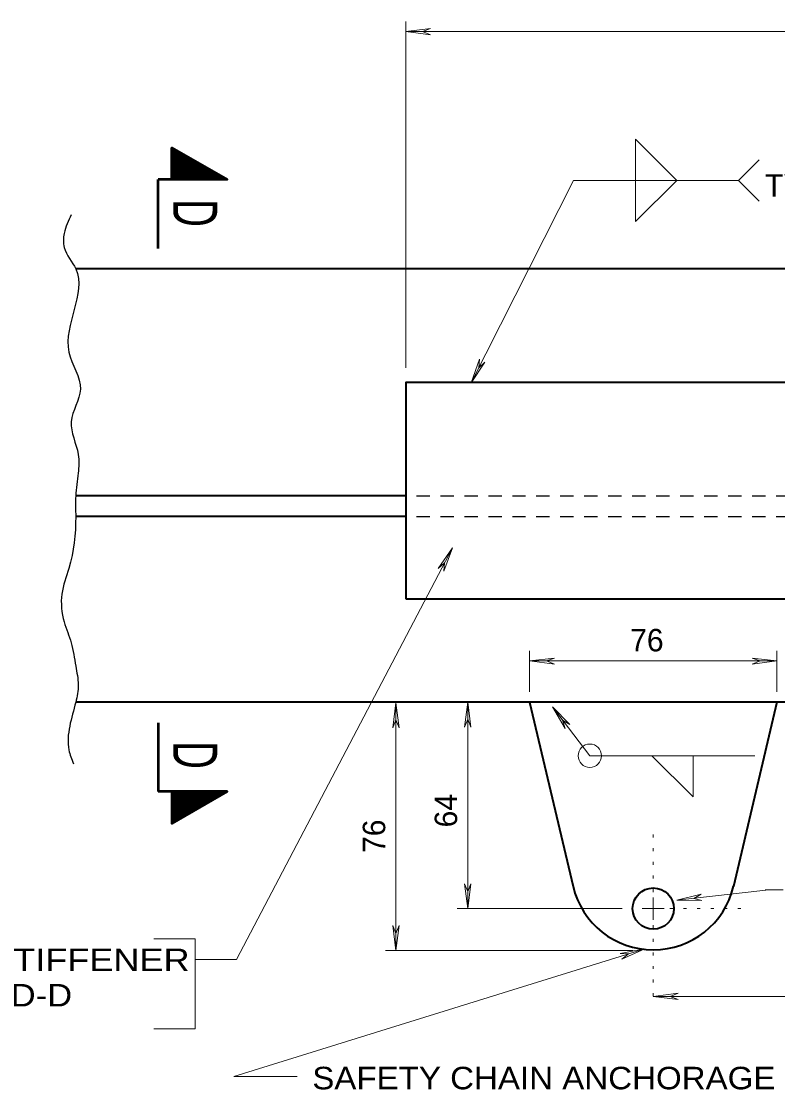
# Model space of a CAD drawing. Extents: x 312583 to 312854, y 144419 to 144597.
# Drawn here: x 312767.21 to 312792.77, y 144484.6 to 144520.68 of the extents above; entities that cross this region are included whole.
import ezdxf
from ezdxf.enums import TextEntityAlignment as Align

# ---------------------------------------------------------------- set-up
doc = ezdxf.new("R2010")
doc.units = 0
doc.header["$LTSCALE"] = 0.3
doc.linetypes.add('DOTTED', pattern=[1.5, 0.3, -1.2])
doc.linetypes.add('SHORT_DASHED', pattern=[2.7, 1.5, -1.2])
doc.layers.add('1', color=7, linetype='Continuous', lineweight=13)

msp = doc.modelspace()

# ---------------------------------------------------------------- linework, layer by layer
at = {"layer": '1'}
for p, q in [((312780.2009, 144508.9729), (312780.2009, 144520.6799)), ((312780.2009, 144520.3349), (312781.0366, 144520.4346)), ((312780.2009, 144520.3349), (312781.0366, 144520.2276)), ((312781.0366, 144520.4346), (312780.7683, 144520.3349)), ((312781.0366, 144520.2276), (312780.7683, 144520.3349)), ((312782.4089, 144508.4746), (312785.8666, 144515.3056)), ((312791.4403, 144515.3056), (312792.1379, 144514.6079)), ((312782.4089, 144508.4746), (312782.6926, 144509.2719)), ((312782.4089, 144508.4746), (312782.8766, 144509.1722)), ((312782.6926, 144509.2719), (312782.6696, 144508.9806)), ((312782.8766, 144509.1722), (312782.6696, 144508.9806)), ((312781.7803, 144502.9009), (312774.4739, 144488.9936)), ((312781.7803, 144502.9009), (312781.2973, 144502.2032)), ((312781.7803, 144502.9009), (312781.4813, 144502.1112)), ((312781.2973, 144502.2032), (312781.5119, 144502.3949)), ((312781.4813, 144502.1112), (312781.5119, 144502.3949)), ((312784.3793, 144499.4202), (312784.3793, 144498.0326)), ((312792.7436, 144499.4202), (312792.7436, 144498.0326)), ((312784.3793, 144499.0752), (312785.2226, 144499.1749)), ((312784.3793, 144499.0752), (312792.7436, 144499.0752)), ((312784.3793, 144499.0752), (312785.2226, 144498.9679)), ((312785.2226, 144499.1749), (312784.9543, 144499.0752)), ((312785.2226, 144498.9679), (312784.9543, 144499.0752)), ((312791.9079, 144499.1749), (312792.1763, 144499.0752)), ((312792.7436, 144499.0752), (312791.9079, 144499.1749)), ((312791.9079, 144498.9679), (312792.1763, 144499.0752)), ((312792.7436, 144499.0752), (312791.9079, 144498.9679)), ((312779.8636, 144497.6569), (312779.7639, 144496.8212)), ((312779.8636, 144489.2926), (312779.8636, 144497.6569)), ((312779.8636, 144497.6569), (312779.9709, 144496.8212)), ((312782.2939, 144497.6799), (312782.1866, 144496.8442)), ((312782.2939, 144490.7109), (312782.2939, 144497.6799)), ((312782.2939, 144497.6799), (312782.3936, 144496.8442)), ((312786.4186, 144495.8706), (312785.1536, 144497.5266)), ((312785.1536, 144497.5266), (312785.7439, 144496.9286)), ((312785.1536, 144497.5266), (312785.5829, 144496.7982)), ((312779.7639, 144496.8212), (312779.8636, 144497.0896)), ((312779.9709, 144496.8212), (312779.8636, 144497.0896)), ((312782.1866, 144496.8442), (312782.2939, 144497.1126)), ((312782.3936, 144496.8442), (312782.2939, 144497.1126)), ((312785.7439, 144496.9286), (312785.4986, 144497.0742)), ((312785.5829, 144496.7982), (312785.4986, 144497.0742)), ((312791.9923, 144495.8706), (312786.4186, 144495.8706)), ((312782.1866, 144491.5466), (312782.2939, 144491.2859)), ((312782.2939, 144490.7109), (312782.1866, 144491.5466)), ((312782.3936, 144491.5466), (312782.2939, 144491.2859)), ((312782.2939, 144490.7109), (312782.3936, 144491.5466)), ((312788.5653, 144490.7109), (312788.5653, 144491.0866)), ((312792.4676, 144491.3472), (312789.3549, 144490.9946)), ((312789.3549, 144490.9946), (312790.1829, 144491.1939)), ((312790.1829, 144491.1939), (312789.9299, 144491.0559)), ((312792.3449, 144491.3472), (312792.9506, 144491.3472)), ((312787.5149, 144490.7109), (312781.9413, 144490.7109)), ((312788.5653, 144490.7109), (312788.1896, 144490.7109)), ((312788.5653, 144490.7109), (312788.9333, 144490.7109)), ((312788.5653, 144490.7109), (312788.5653, 144490.3352)), ((312789.3549, 144490.9946), (312790.2059, 144490.9869)), ((312790.2059, 144490.9869), (312789.9299, 144491.0559)), ((312779.7639, 144490.1359), (312779.8636, 144489.8676)), ((312779.8636, 144489.2926), (312779.7639, 144490.1359)), ((312779.9709, 144490.1359), (312779.8636, 144489.8676)), ((312779.8636, 144489.2926), (312779.9709, 144490.1359)), ((312771.6833, 144489.6912), (312773.0786, 144489.6912)), ((312773.0786, 144486.6476), (312773.0786, 144489.6912)), ((312774.3896, 144485.0343), (312788.2739, 144489.3462)), ((312787.8829, 144489.2926), (312779.5186, 144489.2926)), ((312788.2739, 144489.3462), (312787.4392, 144489.1934)), ((312788.2739, 144489.3462), (312787.5017, 144489.0004)), ((312773.0786, 144488.9936), (312774.4739, 144488.9936)), ((312787.4392, 144489.1934), (312787.7281, 144489.1774)), ((312787.5017, 144489.0004), (312787.7281, 144489.1774)), ((312788.5653, 144487.7439), (312789.4009, 144487.8512)), ((312789.4009, 144487.8512), (312789.1326, 144487.7439)), ((312810.8676, 144487.7439), (312788.5653, 144487.7439)), ((312788.5653, 144487.7439), (312789.4009, 144487.6442)), ((312789.4009, 144487.6442), (312789.1326, 144487.7439)), ((312771.6833, 144486.6476), (312773.0786, 144486.6476)), ((312774.3896, 144485.0343), (312776.5297, 144485.0343))]:
    msp.add_line(p, q, dxfattribs=at)
at = {"layer": '1', "lineweight": 35}
for p, q in [((312772.2966, 144516.3789), (312772.3119, 144516.3942)), ((312772.2966, 144516.3406), (312772.3349, 144516.3866)), ((312772.2966, 144516.2869), (312772.3503, 144516.3712)), ((312772.2966, 144516.2409), (312772.3733, 144516.3559)), ((312772.2966, 144516.1872), (312772.3963, 144516.3482)), ((312772.2966, 144516.1489), (312772.4116, 144516.3406)), ((312772.2966, 144516.1029), (312772.4269, 144516.3252)), ((312772.2966, 144516.0569), (312772.4499, 144516.3176)), ((312772.2966, 144516.0109), (312772.4729, 144516.3099)), ((312772.2966, 144515.9649), (312772.4959, 144516.2946)), ((312772.2966, 144515.9112), (312772.5113, 144516.2869)), ((312772.2966, 144515.8652), (312772.5343, 144516.2716)), ((312772.2966, 144515.8269), (312772.5573, 144516.2639)), ((312772.2966, 144515.7732), (312772.5726, 144516.2486)), ((312772.2966, 144515.7272), (312772.5956, 144516.2409)), ((312772.2966, 144515.6812), (312772.6109, 144516.2256)), ((312772.2966, 144515.6352), (312772.6339, 144516.2102)), ((312772.2966, 144515.5892), (312772.6569, 144516.2026)), ((312772.2966, 144515.5432), (312772.6723, 144516.1872)), ((312772.2966, 144515.4972), (312772.6953, 144516.1719)), ((312772.2966, 144515.4436), (312772.7183, 144516.1642)), ((312772.2966, 144515.4052), (312772.7259, 144516.1489)), ((312772.2966, 144515.3592), (312772.7566, 144516.1412)), ((312772.3119, 144515.3362), (312772.7719, 144516.1259)), ((312772.3426, 144515.3362), (312772.7949, 144516.1259)), ((312772.3733, 144515.3362), (312772.8179, 144516.1029)), ((312772.3963, 144515.3362), (312772.8333, 144516.1029)), ((312772.4269, 144515.3362), (312772.8563, 144516.0799)), ((312772.4499, 144515.3439), (312772.8793, 144516.0799)), ((312772.4729, 144515.3439), (312772.8946, 144516.0646)), ((312772.4959, 144515.3362), (312772.9176, 144516.0569)), ((312772.5266, 144515.3362), (312772.9406, 144516.0416)), ((312772.5573, 144515.3362), (312772.9483, 144516.0262)), ((312772.5803, 144515.3362), (312772.9713, 144516.0186)), ((312772.6109, 144515.3362), (312772.9943, 144516.0032)), ((312772.6416, 144515.3362), (312773.0173, 144515.9879)), ((312772.6646, 144515.3362), (312773.0326, 144515.9802)), ((312772.6953, 144515.3439), (312773.0556, 144515.9649)), ((312772.7183, 144515.3362), (312773.0786, 144515.9572)), ((312772.7413, 144515.3362), (312773.0939, 144515.9419)), ((312772.7643, 144515.3362), (312773.1169, 144515.9342)), ((312772.7949, 144515.3362), (312773.1399, 144515.9189)), ((312772.8256, 144515.3362), (312773.1553, 144515.9112)), ((312772.8563, 144515.3362), (312773.1783, 144515.8959)), ((312772.8793, 144515.3362), (312773.1936, 144515.8882)), ((312772.9099, 144515.3362), (312773.2089, 144515.8806)), ((312772.9329, 144515.3439), (312773.2396, 144515.8652)), ((312772.9636, 144515.3362), (312773.2549, 144515.8576)), ((312772.9789, 144515.3362), (312773.2779, 144515.8346)), ((312773.0096, 144515.3362), (312773.3009, 144515.8346)), ((312773.0403, 144515.3362), (312773.3163, 144515.8192)), ((312773.0633, 144515.3362), (312773.3393, 144515.8116)), ((312773.0939, 144515.3362), (312773.3623, 144515.7962)), ((312773.1246, 144515.3362), (312773.3776, 144515.7886)), ((312773.1476, 144515.3362), (312773.4006, 144515.7732)), ((312773.1783, 144515.3362), (312773.4236, 144515.7656)), ((312773.2089, 144515.3362), (312773.4313, 144515.7502)), ((312773.2243, 144515.3362), (312773.4543, 144515.7426)), ((312773.2473, 144515.3362), (312773.4773, 144515.7272)), ((312773.2779, 144515.3362), (312773.5003, 144515.7196)), ((312773.3086, 144515.3362), (312773.5156, 144515.7042)), ((312773.3393, 144515.3362), (312773.5386, 144515.6889)), ((312773.3623, 144515.3362), (312773.5616, 144515.6812)), ((312773.3929, 144515.3362), (312773.5769, 144515.6659)), ((312773.4083, 144515.3362), (312773.5999, 144515.6506)), ((312773.4389, 144515.3362), (312773.6229, 144515.6429)), ((312773.4619, 144515.3362), (312773.6383, 144515.6352)), ((312773.4926, 144515.3362), (312773.6536, 144515.6199)), ((312773.5233, 144515.3362), (312773.6766, 144515.6122)), ((312773.5463, 144515.3362), (312773.6996, 144515.6046)), ((312773.5769, 144515.3362), (312773.7226, 144515.5892)), ((312773.5999, 144515.3362), (312773.7379, 144515.5816)), ((312773.6306, 144515.3362), (312773.7609, 144515.5662)), ((312773.6536, 144515.3362), (312773.7839, 144515.5586)), ((312773.6766, 144515.3362), (312773.7993, 144515.5432)), ((312773.7073, 144515.3362), (312773.8223, 144515.5356)), ((312773.7303, 144515.3362), (312773.8453, 144515.5202)), ((312773.7609, 144515.3362), (312773.8606, 144515.5049)), ((312773.7916, 144515.3362), (312773.8836, 144515.4972)), ((312773.8223, 144515.3362), (312773.8989, 144515.4819)), ((312773.8453, 144515.3362), (312773.9219, 144515.4666)), ((312773.8759, 144515.3362), (312773.9449, 144515.4589)), ((312773.8989, 144515.3362), (312773.9603, 144515.4436)), ((312773.9219, 144515.3362), (312773.9833, 144515.4359)), ((312773.9449, 144515.3362), (312773.9986, 144515.4206)), ((312773.9756, 144515.3362), (312774.0216, 144515.4129)), ((312774.0063, 144515.3362), (312774.0446, 144515.3976)), ((312774.0293, 144515.3362), (312774.0599, 144515.3899)), ((312774.0599, 144515.3362), (312774.0829, 144515.3746)), ((312774.0829, 144515.3362), (312774.1059, 144515.3669)), ((312774.1136, 144515.3362), (312774.1213, 144515.3592)), ((312774.1443, 144515.3362), (312774.1443, 144515.3439)), ((312772.2966, 144494.6439), (312772.7566, 144493.8542)), ((312772.2966, 144494.5902), (312772.7259, 144493.8466)), ((312772.2966, 144494.5519), (312772.7183, 144493.8312)), ((312772.2966, 144494.4982), (312772.6953, 144493.8236)), ((312772.2966, 144494.4522), (312772.6723, 144493.8082)), ((312772.2966, 144494.4139), (312772.6569, 144493.7929)), ((312772.2966, 144494.3679), (312772.6339, 144493.7852)), ((312772.3119, 144494.6669), (312772.7719, 144493.8696)), ((312772.3426, 144494.6669), (312772.7949, 144493.8772)), ((312772.3733, 144494.6669), (312772.8179, 144493.8926)), ((312772.3963, 144494.6669), (312772.8333, 144493.9002)), ((312772.4269, 144494.6669), (312772.8563, 144493.9156)), ((312772.4499, 144494.6592), (312772.8793, 144493.9232)), ((312772.4729, 144494.6592), (312772.8946, 144493.9386)), ((312772.4959, 144494.6669), (312772.9176, 144493.9386)), ((312772.5266, 144494.6669), (312772.9406, 144493.9616)), ((312772.5573, 144494.6669), (312772.9483, 144493.9692)), ((312772.5803, 144494.6669), (312772.9713, 144493.9846)), ((312772.6109, 144494.6669), (312772.9943, 144493.9922)), ((312772.6416, 144494.6669), (312773.0173, 144494.0076)), ((312772.6646, 144494.6669), (312773.0326, 144494.0152)), ((312772.6953, 144494.6592), (312773.0556, 144494.0306)), ((312772.7183, 144494.6669), (312773.0786, 144494.0382)), ((312772.7413, 144494.6669), (312773.0939, 144494.0536)), ((312772.7643, 144494.6669), (312773.1169, 144494.0612)), ((312772.7949, 144494.6669), (312773.1399, 144494.0766)), ((312772.8256, 144494.6669), (312773.1553, 144494.0842)), ((312772.8563, 144494.6669), (312773.1783, 144494.0996)), ((312772.8793, 144494.6669), (312773.1936, 144494.1072)), ((312772.9099, 144494.6669), (312773.2089, 144494.1226)), ((312772.9329, 144494.6592), (312773.2396, 144494.1302)), ((312772.9636, 144494.6669), (312773.2549, 144494.1456)), ((312772.9789, 144494.6669), (312773.2779, 144494.1609)), ((312773.0096, 144494.6669), (312773.3009, 144494.1686)), ((312773.0403, 144494.6669), (312773.3163, 144494.1839)), ((312773.0633, 144494.6669), (312773.3393, 144494.1839)), ((312773.0939, 144494.6669), (312773.3623, 144494.2069)), ((312773.1246, 144494.6669), (312773.3776, 144494.2069)), ((312773.1476, 144494.6669), (312773.4006, 144494.2299)), ((312773.1783, 144494.6669), (312773.4236, 144494.2299)), ((312773.2089, 144494.6669), (312773.4313, 144494.2452)), ((312773.2243, 144494.6669), (312773.4543, 144494.2529)), ((312773.2473, 144494.6669), (312773.4773, 144494.2682)), ((312773.2779, 144494.6669), (312773.5003, 144494.2759)), ((312773.3086, 144494.6669), (312773.5156, 144494.2912)), ((312773.3393, 144494.6669), (312773.5386, 144494.3066)), ((312773.3623, 144494.6669), (312773.5616, 144494.3142)), ((312773.3929, 144494.6669), (312773.5769, 144494.3296)), ((312773.4083, 144494.6669), (312773.5999, 144494.3449)), ((312773.4389, 144494.6669), (312773.6229, 144494.3526)), ((312773.4619, 144494.6669), (312773.6383, 144494.3679)), ((312773.4926, 144494.6669), (312773.6536, 144494.3756)), ((312773.5233, 144494.6669), (312773.6766, 144494.3909)), ((312773.5463, 144494.6669), (312773.6996, 144494.3986)), ((312773.5769, 144494.6669), (312773.7226, 144494.4139)), ((312773.5999, 144494.6669), (312773.7379, 144494.4216)), ((312773.6306, 144494.6669), (312773.7609, 144494.4292)), ((312773.6536, 144494.6669), (312773.7839, 144494.4446)), ((312773.6766, 144494.6669), (312773.7993, 144494.4522)), ((312773.7073, 144494.6669), (312773.8223, 144494.4599)), ((312773.7303, 144494.6669), (312773.8453, 144494.4752)), ((312773.7609, 144494.6669), (312773.8606, 144494.4906)), ((312773.7916, 144494.6669), (312773.8836, 144494.4982)), ((312773.8223, 144494.6669), (312773.8989, 144494.5136)), ((312773.8453, 144494.6669), (312773.9219, 144494.5289)), ((312773.8759, 144494.6669), (312773.9449, 144494.5366)), ((312773.8989, 144494.6669), (312773.9603, 144494.5519)), ((312773.9219, 144494.6669), (312773.9833, 144494.5596)), ((312773.9449, 144494.6669), (312773.9986, 144494.5749)), ((312773.9756, 144494.6669), (312774.0216, 144494.5826)), ((312774.0063, 144494.6669), (312774.0446, 144494.5979)), ((312774.0293, 144494.6669), (312774.0599, 144494.6056)), ((312774.0599, 144494.6669), (312774.0829, 144494.6209)), ((312774.0829, 144494.6669), (312774.1059, 144494.6286)), ((312774.1136, 144494.6669), (312774.1213, 144494.6439)), ((312774.1443, 144494.6669), (312774.1443, 144494.6516)), ((312772.2966, 144494.3142), (312772.6109, 144493.7699)), ((312772.2966, 144494.2682), (312772.5956, 144493.7546)), ((312772.2966, 144494.2299), (312772.5726, 144493.7469)), ((312772.2966, 144494.1762), (312772.5573, 144493.7392)), ((312772.2966, 144494.1302), (312772.5343, 144493.7239)), ((312772.2966, 144494.0842), (312772.5113, 144493.7162)), ((312772.2966, 144494.0306), (312772.4959, 144493.7086)), ((312772.2966, 144493.9846), (312772.4729, 144493.6932)), ((312772.2966, 144493.9386), (312772.4499, 144493.6856)), ((312772.2966, 144493.9002), (312772.4269, 144493.6702)), ((312772.2966, 144493.8466), (312772.4116, 144493.6626)), ((312772.2966, 144493.8082), (312772.3963, 144493.6472)), ((312772.2966, 144493.7546), (312772.3733, 144493.6396)), ((312772.2966, 144493.7162), (312772.3503, 144493.6242)), ((312772.2966, 144493.6626), (312772.3349, 144493.6089)), ((312772.2966, 144493.6166), (312772.3119, 144493.6012))]:
    msp.add_line(p, q, dxfattribs=at)
at = {"layer": '1', "lineweight": 53}
for p, q in [((312771.8366, 144513.0132), (312771.8366, 144515.3362)), ((312772.2966, 144515.3362), (312771.8366, 144515.3362)), ((312771.8366, 144496.9822), (312771.8366, 144494.6669)), ((312772.2966, 144494.6669), (312771.8366, 144494.6669))]:
    msp.add_line(p, q, dxfattribs=at)
at = {"layer": '1', "lineweight": 40}
for p, q in [((312802.5033, 144512.3156), (312769.0459, 144512.3156)), ((312780.2009, 144504.6489), (312769.0459, 144504.6489)), ((312780.2009, 144503.9512), (312769.0459, 144503.9512)), ((312802.5033, 144497.6799), (312769.0459, 144497.6799)), ((312784.3793, 144497.6799), (312785.8513, 144491.4622)), ((312792.7436, 144497.6799), (312791.2793, 144491.4622))]:
    msp.add_line(p, q, dxfattribs=at)
at = {"layer": '1', "linetype": 'SHORT_DASHED', "lineweight": 25}
for p, q in [((312780.5613, 144504.6489), (312796.5003, 144504.6489)), ((312780.5613, 144503.9512), (312796.5003, 144503.9512))]:
    msp.add_line(p, q, dxfattribs=at)
at = {"layer": '1', "linetype": 'DOTTED'}
for p, q in [((312788.5653, 144491.2706), (312788.5653, 144493.4479)), ((312789.1249, 144490.7109), (312791.6549, 144490.7109)), ((312788.5653, 144490.1512), (312788.5653, 144487.3989))]:
    msp.add_line(p, q, dxfattribs=at)
at = {"layer": '1'}
for points in [[(312802.5033, 144520.3349), (312796.9296, 144520.3349), (312780.2009, 144520.3349)], [(312789.3549, 144515.3056), (312787.9596, 144516.7009), (312787.9596, 144515.3056)], [(312785.8666, 144515.3056), (312791.4403, 144515.3056), (312792.1379, 144516.0032)], [(312789.3549, 144515.3056), (312787.9596, 144513.9179), (312787.9596, 144515.3056)], [(312788.5116, 144495.8706), (312789.9069, 144494.4829), (312789.9069, 144495.8706)]]:
    msp.add_lwpolyline(points, dxfattribs=at)
at = {"layer": '1', "lineweight": 53}
for points in [[(312772.2966, 144515.3362), (312772.2966, 144516.4096), (312774.1596, 144515.3362)], [(312772.2966, 144494.6669), (312772.2966, 144493.5859), (312774.1596, 144494.6669)]]:
    msp.add_lwpolyline(points, close=True, dxfattribs=at)
at = {"layer": '1', "lineweight": 40}
msp.add_lwpolyline([(312780.2009, 144501.1682), (312796.9296, 144501.1682), (312796.9296, 144508.4822), (312780.2009, 144508.4822)], close=True, dxfattribs=at)
at = {"layer": '1'}
msp.add_circle((312786.42, 144495.8741), 0.3942, dxfattribs=at)
at = {"layer": '1', "lineweight": 40}
msp.add_circle((312788.5639, 144490.7109), 0.697, dxfattribs=at)
msp.add_arc((312788.5639, 144492.1042), 2.7872, 193.28615, 346.71385, dxfattribs=at)
at = {"layer": '1', "lineweight": 25}
msp.add_spline([(312768.8926, 144514.1479), (312768.6549, 144513.5192), (312768.6549, 144513.0439), (312769.0459, 144512.3156), (312768.8159, 144509.5096), (312769.2069, 144508.2522), (312768.8926, 144507.1559), (312769.1303, 144506.0519), (312769.1303, 144505.4232), (312769.0459, 144504.6489), (312769.0459, 144503.9512), (312768.8159, 144502.2032), (312768.5783, 144501.3369), (312768.6549, 144500.3939), (312768.8926, 144499.6886), (312769.0459, 144498.8989), (312769.1303, 144498.2702), (312769.0459, 144497.6799), (312768.8159, 144496.0699), (312768.9693, 144495.6022)], degree=3, dxfattribs=at)

# ---------------------------------------------------------------- texts
at = {"layer": '1'}
for s, p in [('TYP', (312792.3409, 144514.754)), ('76', (312787.7822, 144499.3982))]:
    msp.add_text(s, height=0.76, dxfattribs=at).set_placement(p)
at = {"layer": '1', "width": 0.65}
for p in [(312772.3426, 144514.2054), (312772.3426, 144495.8974)]:
    msp.add_text('D', height=1.489, rotation=270, dxfattribs=at).set_placement(p, align=Align.CENTER)
at = {"layer": '1'}
for s, p in [('64', (312781.936, 144493.4527)), ('76', (312779.5057, 144492.5884))]:
    msp.add_text(s, height=0.76, rotation=90, dxfattribs=at).set_placement(p)
for s, width, p in [('6 MM ALUM. STIFFENER', 1.2, (312758.665, 144488.6006)), ('SEE SECTION D-D', 1.15, (312758.665, 144487.4036)), ('SAFETY CHAIN ANCHORAGE LUG', 1.1, (312777.0398, 144484.6059))]:
    msp.add_text(s, height=0.76, dxfattribs=dict(at, width=width)).set_placement(p)

doc.saveas('drawing.dxf')
